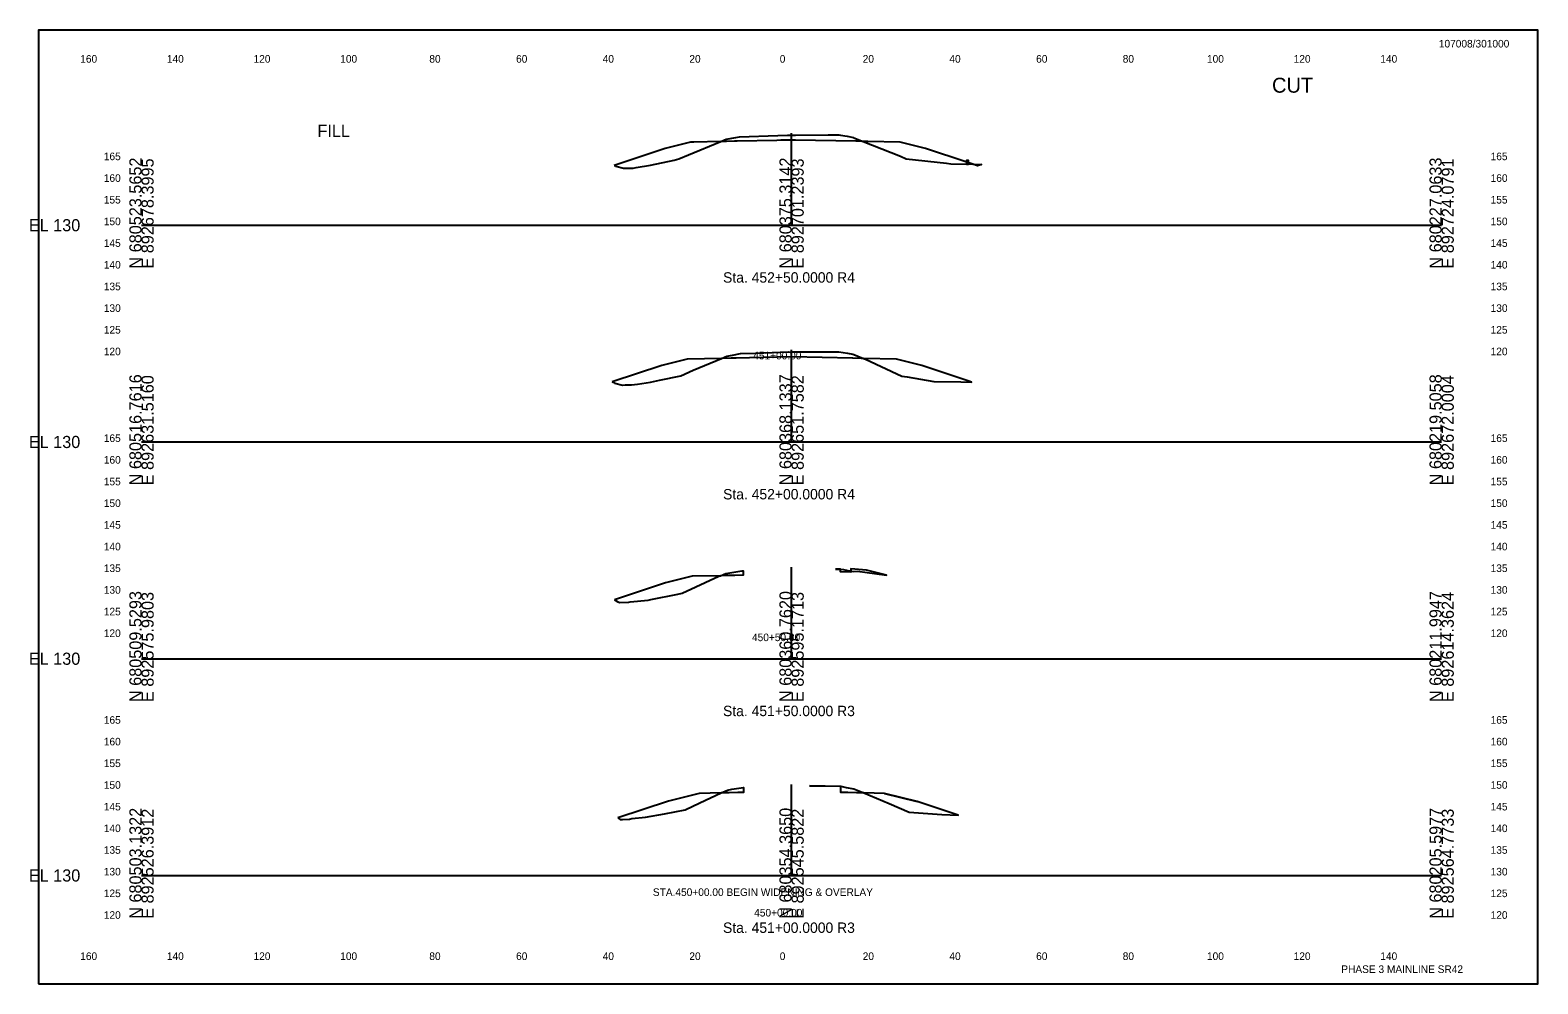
# Model space of a CAD drawing. Extents: x 21059 to 22955, y 6470 to 17494.
# Drawn here: x 21469.1 to 21817, y 6929.8 to 7149.8 of the extents above; entities that cross this region are included whole.
import ezdxf

# ---------------------------------------------------------------- set-up
doc = ezdxf.new("R2010")
doc.units = 0
for name, color, linetype in [('CONST_DCH', 7, 'Continuous'), ('Draft_XS_Grid', 7, 'Continuous'), ('Draft_XS_Text', 7, 'Continuous'), ('DTM CONTOURS_MAJOR', 7, 'Continuous'), ('DTM_TEMP_DROP', 7, 'Continuous'), ('SLOPE_STAKES_FILL', 7, 'Continuous'), ('X_PROFILES_1', 7, 'Continuous'), ('XS_P_SUBGRADE_LEVELING', 7, 'Continuous'), ('XS_P_TX_CLEARZONE', 7, 'Continuous'), ('XS_SHEET_EW_TX_VOLUME', 7, 'Continuous')]:
    doc.layers.add(name, color=color, linetype=linetype)

msp = doc.modelspace()

# ---------------------------------------------------------------- linework, layer by layer
at = {"layer": 'DTM CONTOURS_MAJOR'}
for p, q in [((21644.84, 7104.84), (21644.84, 7126.11)), ((21494.84, 7104.84), (21644.84, 7104.84)), ((21644.84, 7104.84), (21794.84, 7104.84)), ((21644.84, 7054.84), (21644.84, 7076.06)), ((21494.84, 7054.84), (21644.84, 7054.84)), ((21644.84, 7054.84), (21794.84, 7054.84)), ((21644.84, 7004.84), (21644.84, 7025.94)), ((21494.84, 7004.84), (21644.84, 7004.84)), ((21644.84, 7004.84), (21794.84, 7004.84)), ((21644.84, 6954.84), (21644.84, 6975.82)), ((21494.84, 6954.84), (21644.84, 6954.84)), ((21644.84, 6954.84), (21794.84, 6954.84))]:
    msp.add_line(p, q, dxfattribs=at)
at = {"layer": 'DTM_TEMP_DROP'}
msp.add_lwpolyline([(21471.04, 6929.84), (21817.04, 6929.84), (21817.04, 7149.84), (21471.04, 7149.84)], close=True, dxfattribs=at)
at = {"layer": 'XS_P_TX_CLEARZONE'}
for points in [[(21621.88, 7023.86), (21615.71, 7022.32)], [(21623.49, 6973.77), (21616.43, 6972.01)], [(21666.31, 6973.77), (21673.79, 6971.9)]]:
    msp.add_lwpolyline(points, dxfattribs=at)
at = {"layer": 'XS_SHEET_EW_TX_VOLUME'}
for points in [[(21628.5, 7124.15), (21629.76, 7124.66), (21631.95, 7125.1), (21632.84, 7125.25), (21641.69, 7125.56), (21643.91, 7125.65), (21645.7, 7125.64), (21645.71, 7125.64), (21653.31, 7125.67), (21655.78, 7125.67), (21656.11, 7125.64), (21657.63, 7125.35), (21659.15, 7125.06), (21659.21, 7125.03), (21661.35, 7124.18), (21659.85, 7124.21), (21659.7, 7124.21), (21645.74, 7124.49), (21645.7, 7124.49), (21645.66, 7124.49), (21645.12, 7124.48), (21642.33, 7124.43), (21641.44, 7124.41), (21632.32, 7124.23), (21631.69, 7124.21), (21629.81, 7124.18), (21629.69, 7124.17)], [(21603.88, 7118.62), (21604.03, 7118.58), (21604.3, 7118.48), (21606.08, 7118), (21607.71, 7118.03), (21608.27, 7118.02), (21608.97, 7118.16), (21612.29, 7118.72), (21617.71, 7119.86), (21618.81, 7120.15), (21621.04, 7121.1), (21628.5, 7124.15), (21622.29, 7124.03), (21621.52, 7124.01), (21615.69, 7122.55)], [(21661.35, 7124.18), (21670, 7120.74), (21671.3, 7120.13), (21680.59, 7119.17), (21681.6, 7118.99), (21686.67, 7118.9), (21685.3, 7119.36), (21675.71, 7122.55), (21669.88, 7124.01), (21662.41, 7124.16), (21661.7, 7124.17)], [(21685.19, 7119.81), (21685.19, 7118.93), (21685.69, 7118.92), (21685.69, 7119.78)], [(21686.67, 7118.9), (21688.21, 7118.88), (21688.67, 7118.86), (21688.67, 7118.86), (21687.73, 7118.55)], [(21603.43, 7068.68), (21603.85, 7068.57), (21604.04, 7068.44), (21605.83, 7067.96), (21606.45, 7067.99), (21607.89, 7068.01), (21609.26, 7068.16), (21612.29, 7068.67), (21614.37, 7069.09), (21619.25, 7070.12), (21622.11, 7071.44), (21628.66, 7074.12), (21620.86, 7073.96), (21620.73, 7073.96), (21614.91, 7072.5)], [(21628.66, 7074.12), (21629.93, 7074.64), (21631.17, 7074.83), (21633.07, 7075.21), (21636.49, 7075.33), (21644.15, 7075.6), (21644.48, 7075.59), (21644.92, 7075.62), (21649.13, 7075.6), (21655.74, 7075.6), (21657.74, 7075.34), (21658.99, 7075.1), (21659.19, 7075), (21661.43, 7074.11), (21661.1, 7074.12), (21660.91, 7074.12), (21658.95, 7074.16), (21658.91, 7074.16), (21644.91, 7074.44), (21644.86, 7074.44), (21638.2, 7074.31), (21632.07, 7074.18), (21630.93, 7074.16), (21630.91, 7074.16), (21628.92, 7074.12), (21628.91, 7074.12)], [(21661.43, 7074.11), (21661.87, 7073.94), (21670.27, 7070), (21671.54, 7069.87), (21677.65, 7068.8), (21683.86, 7068.69), (21686.39, 7068.67), (21685.71, 7068.9), (21674.91, 7072.5), (21669.08, 7073.96)], [(21604, 7018.42), (21604.14, 7018.38), (21604.78, 7017.95), (21605.19, 7017.84), (21607.27, 7017.92), (21607.58, 7017.93), (21611.72, 7018.37), (21612.38, 7018.48), (21618.59, 7019.74), (21619.61, 7019.96), (21628.05, 7023.85), (21628.4, 7023.99), (21621.88, 7023.86), (21615.71, 7022.32)], [(21628.4, 7023.99), (21629.68, 7024.52), (21633.34, 7025.08), (21633.63, 7025.14), (21633.63, 7024.85), (21633.63, 7024.1), (21631.71, 7024.06), (21629.71, 7024.02)], [(21655.01, 7025.49), (21656.12, 7025.49), (21656.83, 7025.4), (21658.53, 7025.06), (21658.53, 7024.8), (21656.12, 7024.85), (21656.12, 7025.47)], [(21658.53, 7025.06), (21659.11, 7024.94), (21660.06, 7025.04), (21666.72, 7024.14), (21662.14, 7025.29), (21658.53, 7025.55)], [(21648.94, 6975.49), (21651.78, 6975.48), (21656.18, 6975.4), (21657.44, 6975.16), (21659.19, 6974.81), (21661.49, 6973.87), (21659.79, 6973.9), (21657.79, 6973.94), (21656.18, 6973.97), (21656.18, 6974.72), (21656.18, 6975.35)], [(21604.72, 6968.11), (21604.97, 6967.94), (21605.25, 6967.78), (21605.8, 6967.74), (21607.44, 6967.81), (21607.95, 6967.95), (21611.12, 6968.29), (21615.54, 6969.04), (21620.25, 6970), (21623.69, 6971.61), (21628.59, 6973.88), (21623.49, 6973.77), (21616.43, 6972.01)], [(21628.59, 6973.88), (21630.03, 6974.54), (21631.09, 6974.75), (21633.71, 6975.16), (21633.71, 6974.73), (21633.71, 6973.98), (21632.43, 6973.95), (21630.43, 6973.91)], [(21661.49, 6973.87), (21667.39, 6971.45), (21671.95, 6969.45), (21679.54, 6968.93), (21683.28, 6968.74), (21673.79, 6971.9), (21666.31, 6973.77)]]:
    msp.add_lwpolyline(points, close=True, dxfattribs=at)

# ---------------------------------------------------------------- texts
at = {"layer": 'CONST_DCH'}
for p in [(21603.84, 7118.56), (21603.84, 7118.56), (21687.69, 7118.49), (21687.69, 7118.49), (21603.39, 7068.62), (21603.39, 7068.62), (21686.35, 7068.61), (21686.35, 7068.61)]:
    msp.add_text('X', height=0.12, dxfattribs=at).set_placement(p)
at = {"layer": 'Draft_XS_Grid'}
for s, p in [('  165  ', (21484.84, 7119.84)), ('  165  ', (21804.84, 7119.84)), ('  160  ', (21484.84, 7114.84)), ('  160  ', (21804.84, 7114.84)), ('  155  ', (21484.84, 7109.84)), ('  155  ', (21804.84, 7109.84)), ('  150  ', (21484.84, 7104.84)), ('  150  ', (21804.84, 7104.84)), ('  145  ', (21484.84, 7099.84)), ('  145  ', (21804.84, 7099.84)), ('  140  ', (21484.84, 7094.84)), ('  140  ', (21804.84, 7094.84)), ('  135  ', (21484.84, 7089.84)), ('  135  ', (21804.84, 7089.84)), ('  130  ', (21484.84, 7084.84)), ('  130  ', (21804.84, 7084.84)), ('  125  ', (21484.84, 7079.84)), ('  125  ', (21804.84, 7079.84)), ('  120  ', (21484.84, 7074.84)), ('  120  ', (21804.84, 7074.84)), ('  165  ', (21484.84, 7054.84)), ('  165  ', (21804.84, 7054.84)), ('  160  ', (21484.84, 7049.84)), ('  160  ', (21804.84, 7049.84)), ('  155  ', (21484.84, 7044.84)), ('  155  ', (21804.84, 7044.84)), ('  150  ', (21484.84, 7039.84)), ('  150  ', (21804.84, 7039.84)), ('  145  ', (21484.84, 7034.84)), ('  145  ', (21804.84, 7034.84)), ('  140  ', (21484.84, 7029.84)), ('  140  ', (21804.84, 7029.84)), ('  135  ', (21484.84, 7024.84)), ('  135  ', (21804.84, 7024.84)), ('  130  ', (21484.84, 7019.84)), ('  130  ', (21804.84, 7019.84)), ('  125  ', (21484.84, 7014.84)), ('  125  ', (21804.84, 7014.84)), ('  120  ', (21484.84, 7009.84)), ('  120  ', (21804.84, 7009.84)), ('  165  ', (21484.84, 6989.84)), ('  165  ', (21804.84, 6989.84)), ('  160  ', (21484.84, 6984.84)), ('  160  ', (21804.84, 6984.84)), ('  155  ', (21484.84, 6979.84)), ('  155  ', (21804.84, 6979.84)), ('  150  ', (21484.84, 6974.84)), ('  150  ', (21804.84, 6974.84)), ('  145  ', (21484.84, 6969.84)), ('  145  ', (21804.84, 6969.84)), ('  140  ', (21484.84, 6964.84)), ('  140  ', (21804.84, 6964.84)), ('  135  ', (21484.84, 6959.84)), ('  135  ', (21804.84, 6959.84)), ('  130  ', (21484.84, 6954.84)), ('  130  ', (21804.84, 6954.84)), ('  125  ', (21484.84, 6949.84)), ('  125  ', (21804.84, 6949.84)), ('  120  ', (21484.84, 6944.84)), ('  120  ', (21804.84, 6944.84))]:
    msp.add_text(s, height=1.75, dxfattribs=at).set_placement(p)
at = {"layer": 'Draft_XS_Text'}
for s, height, p in [('107008/301000', 1.75, (21794.19, 7145.84)), ('  160  ', 1.75, (21479.4, 7142.34)), ('  140  ', 1.75, (21499.39, 7142.34)), ('  120  ', 1.75, (21519.39, 7142.34)), ('  100  ', 1.75, (21539.39, 7142.34)), ('  80  ', 1.75, (21559.95, 7142.34)), ('  60  ', 1.75, (21579.97, 7142.34)), ('  40  ', 1.75, (21599.95, 7142.34)), ('  20  ', 1.75, (21619.95, 7142.34)), ('  0  ', 1.75, (21640.81, 7142.34)), ('  0  ', 1.75, (21640.81, 7142.34)), ('  20  ', 1.75, (21659.95, 7142.34)), ('  40  ', 1.75, (21679.95, 7142.34)), ('  60  ', 1.75, (21699.97, 7142.34)), ('  80  ', 1.75, (21719.95, 7142.34)), ('  100  ', 1.75, (21739.39, 7142.34)), ('  120  ', 1.75, (21759.39, 7142.34)), ('  140  ', 1.75, (21779.39, 7142.34)), ('CUT', 3.455, (21755.7, 7135.41)), ('FILL', 2.801, (21535.44, 7125.2)), ('  160  ', 1.75, (21479.4, 6935.34)), ('  140  ', 1.75, (21499.39, 6935.34)), ('  120  ', 1.75, (21519.39, 6935.34)), ('  100  ', 1.75, (21539.39, 6935.34)), ('  80  ', 1.75, (21559.95, 6935.34)), ('  60  ', 1.75, (21579.97, 6935.34)), ('  40  ', 1.75, (21599.95, 6935.34)), ('  20  ', 1.75, (21619.95, 6935.34)), ('  0  ', 1.75, (21640.81, 6935.34)), ('  0  ', 1.75, (21640.81, 6935.34)), ('  20  ', 1.75, (21659.95, 6935.34)), ('  40  ', 1.75, (21679.95, 6935.34)), ('  60  ', 1.75, (21699.97, 6935.34)), ('  80  ', 1.75, (21719.95, 6935.34)), ('  100  ', 1.75, (21739.39, 6935.34)), ('  120  ', 1.75, (21759.39, 6935.34)), ('  140  ', 1.75, (21779.39, 6935.34)), ('PHASE 3 MAINLINE SR42', 1.75, (21771.68, 6932.34))]:
    msp.add_text(s, height=height, dxfattribs=at).set_placement(p)
at = {"layer": 'DTM CONTOURS_MAJOR'}
for s, p in [('N 680523.5652', (21494.84, 7094.84)), ('E 892678.3995', (21497.64, 7094.84)), ('N 680375.3142', (21644.84, 7094.84)), ('E 892701.2393', (21647.64, 7094.84)), ('N 680227.0633', (21794.84, 7094.84)), ('E 892724.0791', (21797.64, 7094.84)), ('N 680516.7616', (21494.84, 7044.84)), ('E 892631.5160', (21497.64, 7044.84)), ('N 680368.1337', (21644.84, 7044.84)), ('E 892651.7582', (21647.64, 7044.84)), ('N 680219.5058', (21794.84, 7044.84)), ('E 892672.0004', (21797.64, 7044.84)), ('N 680509.5293', (21494.84, 6994.84)), ('E 892575.9803', (21497.64, 6994.84)), ('N 680360.7620', (21644.84, 6994.84)), ('E 892595.1713', (21647.64, 6994.84)), ('N 680211.9947', (21794.84, 6994.84)), ('E 892614.3624', (21797.64, 6994.84)), ('N 680503.1322', (21494.84, 6944.84)), ('E 892526.3912', (21497.64, 6944.84)), ('N 680354.3650', (21644.84, 6944.84)), ('E 892545.5822', (21647.64, 6944.84)), ('N 680205.5977', (21794.84, 6944.84)), ('E 892564.7733', (21797.64, 6944.84))]:
    msp.add_text(s, height=2.8, rotation=90, dxfattribs=at).set_placement(p)
for p in [(21468.84, 7103.44), (21468.84, 7053.44), (21468.84, 7003.44), (21468.84, 6953.44)]:
    msp.add_text('EL 130', height=2.8, dxfattribs=at).set_placement(p)
at = {"layer": 'SLOPE_STAKES_FILL'}
for s, p in [('  451+00.00  ', (21634.69, 7073.89)), ('  450+50.00  ', (21634.4, 7008.89)), (' STA.450+00.00 BEGIN WIDENING & OVERLAY', (21612.18, 6950.11)), ('  450+00.00  ', (21634.91, 6945.37))]:
    msp.add_text(s, height=1.75, dxfattribs=at).set_placement(p)
at = {"layer": 'X_PROFILES_1'}
for s, p in [('Sta. 452+50.0000 R4', (21629.03, 7091.59)), ('Sta. 452+00.0000 R4', (21629.03, 7041.59)), ('Sta. 451+50.0000 R3', (21629.02, 6991.59)), ('Sta. 451+00.0000 R3', (21629.02, 6941.59))]:
    msp.add_text(s, height=2.4, dxfattribs=at).set_placement(p)
at = {"layer": 'XS_P_SUBGRADE_LEVELING'}
for p in [(21666.69, 7024.08), (21603.96, 7018.36), (21683.24, 6968.68), (21604.68, 6968.05)]:
    msp.add_text('X', height=0.12, dxfattribs=at).set_placement(p)

doc.saveas('drawing.dxf')
